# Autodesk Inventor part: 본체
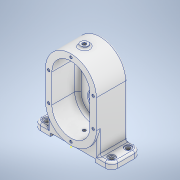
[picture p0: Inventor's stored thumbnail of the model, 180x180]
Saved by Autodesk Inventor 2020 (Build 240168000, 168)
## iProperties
Created: 2021-05
Part Number: 본체
Material: 알루미늄 6061
Document SubType Name: Modeling
Designer: Owner
Density: 2.7 g/cm^3
Appearance: 알루미늄 - 평지
Mass: 756.279 g
Surface Area: 582.903 cm^2
Volume: 280.103 cm^3
Author: Owner
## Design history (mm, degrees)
sketch "스케치2"
  geometry: L1 (0, 22.5)-(0, -22.5); L2 (-40, 22.5)-(-40, -22.5); L3 (40, -22.5)-(40, 22.5); A1 r 40 centre (0, 22.5) between (40, 22.5) and (-40, 22.5); A2 r 40 centre (0, -22.5) between (-40, -22.5) and (40, -22.5); 2 further points
  constraints: 8 end point, 4 point on circle, 4 tangent, 2 centre point, 1 coincident, 1 midpoint, 1 parallel, 1 vertical
  dimensions: "d3" = 40 radius of A1; "d4" = 45 distance of L1.end L1.start
extrude "돌출1" new body sketch "스케치2" distance "d5" = 49; taper "d6" = 0 deg
sketch "스케치3"
  geometry: L1 (0, 22.5)-(0, -22.5); L2 (-30, 22.5)-(-30, -22.5); L3 (30, -22.5)-(30, 22.5); A1 r 30 centre (0, 22.5) between (30, 22.5) and (-30, 22.5); A2 r 30 centre (0, -22.5) between (-30, -22.5) and (30, -22.5); 2 further points
  constraints: 8 end point, 4 point on circle, 4 tangent, 2 centre point, 1 coincident, 1 midpoint, 1 parallel, 1 vertical
  dimensions: "d7" = 30 radius of A1; "d8" = 45 distance of L1.end L1.start
extrude "돌출2" cut sketch "스케치3" distance "d9" = 41; taper "d10" = 0 deg
sketch "스케치4"
  geometry: L1 (-30, -22.5)-(-30, 22.5) reference; L2 (30, 22.5)-(30, -22.5) reference; L3 (-30, -22.5)-(-30, 22.5) reference; C1 r 10 at (0, -22.5); C2 r 14 at (0, -22.5); A1 r 30 centre (0, -22.5) between (-30, -22.5) and (30, -22.5) reference; A2 r 30 centre (0, -22.5) between (-30, -22.5) and (30, -22.5) reference; A3 r 30 centre (0, 22.5) between (30, 22.5) and (-30, 22.5) reference; 1 further point
  constraints: 2 centre point, 2 coincident
  dimensions: "d11" = 28 diameter of C2; "d12" = 20 diameter of C1
  node "투영된 루프1"
sketch "스케치5"
  geometry: C1 r 11 at (0, 22.5); C2 r 14 at (0, 22.5); 1 further point
  constraints: 2 centre point, 1 coincident
  dimensions: "d13" = 22.5 distance of point (0, 0) C1.centre; "d14" = 22 diameter of C1; "d15" = 28 diameter of C2
extrude "돌출3" cut sketch "스케치5" distance "d16" = 41; taper "d17" = 0 deg
extrude "돌출4" join sketch "스케치5" distance "d18" = 8; taper "d19" = 0 deg
extrude "돌출9" cut sketch "스케치5" distance "d32" = 8; taper "d33" = 0 deg
sketch "스케치9"
  geometry: 1 further point
sketch "스케치10"
  geometry: L1 (0, 22.5)-(0, -22.5); L2 (-26, 22.5)-(-26, -22.5); L3 (26, -22.5)-(26, 22.5); A1 r 40 centre (0, 22.5) between (40, 22.5) and (-40, 22.5) reference; A2 r 40 centre (0, -22.5) between (-40, -22.5) and (40, -22.5) reference; A3 r 26 centre (0, 22.5) between (26, 22.5) and (-26, 22.5); A4 r 26 centre (0, -22.5) between (-26, -22.5) and (26, -22.5); 2 further points
  constraints: 8 end point, 4 point on circle, 4 tangent, 2 centre point, 1 midpoint, 1 parallel, 1 vertical
  dimensions: "d41" = 26 radius of A3
extrude "돌출13" join sketch "스케치10" distance "d42" = 11; taper "d43" = 0 deg
sketch "스케치11"
  geometry: L1 (-26, -22.5)-(-26, 22.5) reference; L2 (-26, -7.5)-(26, -7.5); L3 (26, -22.5)-(26, 22.5) reference; A1 r 26 centre (0, 22.5) between (26, 22.5) and (-26, 22.5) reference; 1 further point
  constraints: 2 end point, 2 point on line, 1 horizontal
  dimensions: "d44" = 30 distance from line of L2 A1.centre
extrude "돌출14" cut sketch "스케치11" distance "d45" = 3; taper "d46" = 0 deg
extrude "돌출15" cut sketch "스케치5" distance "d47" = 54.25; taper "d48" = 0 deg
sketch "스케치12"
  geometry: C1 r 11 at (0, 22.5) reference; C2 r 14 at (0, 22.5); 1 further point
  constraints: 1 centre point, 1 coincident
  dimensions: "d49" = 28 diameter of C2
extrude "돌출16" cut sketch "스케치12" distance "d50" = 3; taper "d51" = 0 deg
extrude "돌출17" cut sketch "스케치4" distance "d52" = 12; taper "d53" = 0 deg
extrude "돌출18" cut sketch "스케치4" distance "d54" = 8; taper "d55" = 0 deg
sketch "스케치13"
  geometry: L1 (0, 22.5)-(0, -22.5); L2 (-35, 22.5)-(-35, -22.5); L3 (35, -22.5)-(35, 22.5); C1 r 11 at (0, 22.5) reference; A1 r 40 centre (0, 22.5) between (40, 22.5) and (-40, 22.5) reference; A2 r 40 centre (0, -22.5) between (-40, -22.5) and (40, -22.5) reference; A3 r 35 centre (0, 22.5) between (35, 22.5) and (-35, 22.5); A4 r 35 centre (0, -22.5) between (-35, -22.5) and (35, -22.5); 8 further points
  constraints: 8 end point, 6 point on circle, 4 coincident, 4 tangent, 2 centre point, 1 midpoint, 1 parallel, 1 vertical
  dimensions: "d56" = 35 radius of A3
hole "구멍1" sketch "스케치13" at (-35, 22.5), (35, 22.5), (0, 57.5), (-35, -22.5), (35, -22.5), (0, -57.5) diameter "d57" = 3.242; stored, may be unused: countersink angle "d61" = 90 deg, drill point angle "d63" = 118 deg; dims "d58" = 8, "d59" = 4, "d60" = 2, "d62" = 10
chamfer "모따기1" distance "d64" = 0.4; stored, may be unused: second distance "d65" = 2, angle "d66" = 45 deg
sketch "스케치14" dims "d67" = 40
  geometry: C1 r 11 at (0, 22.5) reference; 3 further points
  constraints: 1 coincident, 1 vertical alignment, 2 other
hole "구멍2" sketch "스케치14" at (0, 42.5) diameter "d68" = 3.242; stored, may be unused: countersink angle "d72" = 90 deg, drill point angle "d74" = 118 deg; dims "d69" = 8, "d70" = 4, "d71" = 2, "d73" = 10
chamfer "모따기2" distance "d75" = 0.4; stored, may be unused: second distance "d76" = 2, angle "d77" = 45 deg
node "작업 평면1"
sketch "스케치15"
  geometry: L1 (40, 0)-(-40, 0) reference; L2 (0, -75.608)-(0, 31.193); C1 r 6 at (0, -21); 1 further point
  constraints: 2 end point, 2 point on line, 1 centre point, 1 vertical
  dimensions: "d84" = 21 distance from line of L1 C1.centre; "d85" = 12 diameter of C1
extrude "돌출19" join sketch "스케치15" stored distance "d86" = 8; taper "d87" = 0 deg
sketch "스케치16"
  geometry: 2 further points
hole "구멍3" sketch "스케치16" at (0, 0) diameter "d88" = 4.917; stored, may be unused: countersink angle "d92" = 90 deg, drill point angle "d94" = 118 deg; dims "d89" = 12, "d90" = 4, "d91" = 2, "d93" = 60.25
chamfer "모따기3" distance "d95" = 0.6; stored, may be unused: second distance "d96" = 2, angle "d97" = 45 deg
node "작업 평면2"
sketch "스케치17"
  geometry: L1 (-61, 28)-(-35, 28); L2 (-35, 28)-(-35, -18); L3 (-35, -18)-(-61, -18); L4 (-61, -18)-(-61, 28); L5 (-40, -21)-(40, -21) reference; L6 (0, 97.296)-(0, -92.171); L7 (61, 28)-(35, 28); L8 (35, 28)-(35, -18); L9 (35, -18)-(61, -18); L10 (61, -18)-(61, 28); C1 r 3.058 at (0, 0) reference; 1 further point
  constraints: 18 end point, 4 symmetric about line, 2 parallel, 1 horizontal, 1 perpendicular, 1 point on line, 1 vertical
  dimensions: "d99" = 46 distance of L3.end L1.start; "d100" = 3 distance between parallel lines of L5 L3; "d101" = 122 distance between parallel lines of L10 L4; "d102" = 70 distance between parallel lines of L8 L2
extrude "돌출20" join sketch "스케치17" distance "d103" = 10; taper "d104" = 0 deg
sketch "스케치18"
  geometry: L1 (-40, -22.5)-(-40, -59.5); L2 (-35, -59.5)-(-61, -59.5) reference; L3 (40, -22.5)-(40, -59.5); L4 (-35, -69.5)-(-35, -59.5) reference; L5 (35, -69.5)-(35, -59.5) reference; L6 (-35, -64.5)-(35, -64.5); L7 (35, -69.5)-(61, -69.5) reference; L8 (-61, -59.5)-(-35, -59.5) reference; L9 (-40, -59.5)-(-35, -59.5); L10 (-35, -59.5)-(-35, -64.5); L11 (35, -64.5)-(35, -59.5); L12 (35, -59.5)-(40, -59.5); L13 (61, -59.5)-(35, -59.5) reference; A1 r 40 centre (0, -22.5) between (-40, -22.5) and (40, -22.5) reference; 1 further point
  constraints: 14 end point, 2 collinear, 2 midpoint, 2 perpendicular, 2 vertical, 1 horizontal, 1 point on line
  dimensions: "d105" = 5 distance between parallel lines of L7 L6
extrude "돌출21" join sketch "스케치18" distance "d106" = 46; taper "d107" = 0 deg
fillet "모깎기1" dims "d108" = 10
sketch "스케치19"
  geometry: L1 (-77.597, 5)-(73.373, 5); C1 r 5.5 at (-51, 18); C2 r 5.5 at (-51, -8); C3 r 5.5 at (51, -8); C4 r 5.5 at (51, 18); C5 r 3.3 at (-51, -8); C6 r 5.5 at (-51, 18); C7 r 3.3 at (-51, 18); A1 r 10 centre (-51, 18) between (-51, 28) and (-61, 18) reference; A2 r 10 centre (-51, -8) between (-61, -8) and (-51, -18) reference; A3 r 10 centre (51, -8) between (51, -18) and (61, -8) reference; A4 r 10 centre (51, 18) between (61, 18) and (51, 28) reference; 2 further points
  constraints: 7 centre point, 7 coincident, 2 end point, 2 symmetric about line, 1 horizontal, 1 other
  dimensions: "d109" = 11 diameter of C2; "d110" = 11 diameter of C1; "d111" = 11 diameter of C3; "d112" = 11 diameter of C4; "d113" = 6.6 diameter of C5; "d118" = 6.6 diameter of C7
extrude "돌출22" cut sketch "스케치19" distance "d114" = 2; taper "d115" = 0 deg
extrude "돌출23" cut sketch "스케치19" distance "d116" = 27.5; taper "d117" = 0 deg
extrude "돌출24" cut sketch "스케치19" distance "d119" = 1; taper "d120" = 0 deg
extrude "돌출25" cut sketch "스케치19" distance "d121" = 14.5; taper "d122" = 0 deg
sketch "스케치20"
  geometry: 1 further point
sketch "스케치21"
  geometry: C1 r 3.058 at (35, 28) reference; C2 r 6 at (35, 28); 2 further points
  constraints: 2 coincident, 1 centre point
  dimensions: "d123" = 12 diameter of C2
extrude "돌출26" cut sketch "스케치21" distance "d124" = 1; taper "d125" = 0 deg
sketch "스케치22"
  geometry: C1 r 3.058 at (0, 0) reference; 2 further points
  constraints: 1 coincident
hole "구멍4" sketch "스케치22" at (0, 0) diameter "d126" = 4.917; stored, may be unused: countersink angle "d130" = 90 deg, drill point angle "d132" = 118 deg; dims "d127" = 12, "d128" = 4, "d129" = 2, "d131" = 9.75
fillet "모깎기2" dims "d133" = 3
fillet "모깎기3" dims "d134" = 3
fillet "모깎기4" dims "d135" = 5
chamfer "모따기4" distance "d136" = 1; stored, may be unused: second distance "d137" = 2, angle "d138" = 45 deg
chamfer "모따기5" distance "d139" = 1; stored, may be unused: second distance "d140" = 2, angle "d141" = 45 deg
sketch "스케치23"
  geometry: 1 further point
sketch "스케치24"
  geometry: L1 (-8.882, -57.5)-(11.523, -57.5); L2 (-35, -64.5)-(35, -64.5) reference; L3 (35, -69.5)-(51, -69.5) reference; L4 (-16.731, -54.975)-(15.58, -54.975); L5 (15.58, -54.975)-(15.58, -59.778); L6 (15.58, -59.778)-(-16.731, -59.778); L7 (-16.731, -59.778)-(-16.731, -54.975); 1 further point
  constraints: 2 end point, 1 horizontal, 2 other
  dimensions: "d143" = 12 distance between parallel lines of L3 L1
feature "엠보싱1" sketch "스케치24" dims "d144" = 1, "d145" = 0
node "솔리드1"
pattern_circular "원형 패턴1" dims angle "d79" = 360 deg
mirror "미러1"
mirror "미러2"
feature "A9D066F2-1C7D-4E18-AEED-F7BC21143FA4" dims "d57" = 3.242, "d58" = 8, "d59" = 4, "d60" = 2, "d61" = 90 deg, "d62" = 10, "d63" = 118 deg
other parameters: "d81" = 65.5, "d98" = -135
